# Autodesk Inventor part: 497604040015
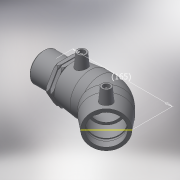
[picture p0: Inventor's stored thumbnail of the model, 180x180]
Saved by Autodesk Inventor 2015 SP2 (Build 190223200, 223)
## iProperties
Created: 2017-06
Part Number: 497604040015
Material: Generic
Description: PLASSON PE MALE TRANSITION 45° ELBOW 40-1.1/2"
Document SubType Name: Modeling
Designer: KIM
Mass: 55.0731 g
Surface Area: 148.067 cm^2
Volume: 55.0731 cm^3
Density: 1 g/cm^3
Appearance: Default
Author: KIM
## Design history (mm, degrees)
derived "497604.ipt"
feature "Solid1::497604.ipt"
tag "TaggingFeature1"
body "Solid1"
other parameters: "d2" = 56, "d4" = 26.5, "d5" = 50.4, "d8" = 168 deg, "d10" = 16.8, "d11" = 5.6, "d29" = 47, "d30" = 15, "d31" = 37.1, "d34" = 5 deg, "d41" = 4, "d42" = 14, "d43" = 0, "d50" = 34, "d51" = 16.8, "d52" = 41.9, "d54" = 135 deg, "d86" = 25.2, "d87" = 135 deg, "d88" = 106, "d90" = 33.6, "d91" = 0, "d92" = 42, "d93" = 0, "d101" = 3, "d102" = 0, "d107" = 0.1, "d109" = 47.803, "d110" = 42, "d111" = 10.5, "d112" = 56, "d113" = 33.4621, "d114" = 37.8, "d116" = 1.68, "d122" = 0, "d123" = 2.39015, "d126" = 1.05, "d127" = 4.725, "d128" = 56, "d130" = 42, "L_" = 148, "L_2" = 42, "A_" = 47, "d_2" = 12, "L_1" = 42, "R_" = 47.803, "D_1" = 56, "d129" = 148
